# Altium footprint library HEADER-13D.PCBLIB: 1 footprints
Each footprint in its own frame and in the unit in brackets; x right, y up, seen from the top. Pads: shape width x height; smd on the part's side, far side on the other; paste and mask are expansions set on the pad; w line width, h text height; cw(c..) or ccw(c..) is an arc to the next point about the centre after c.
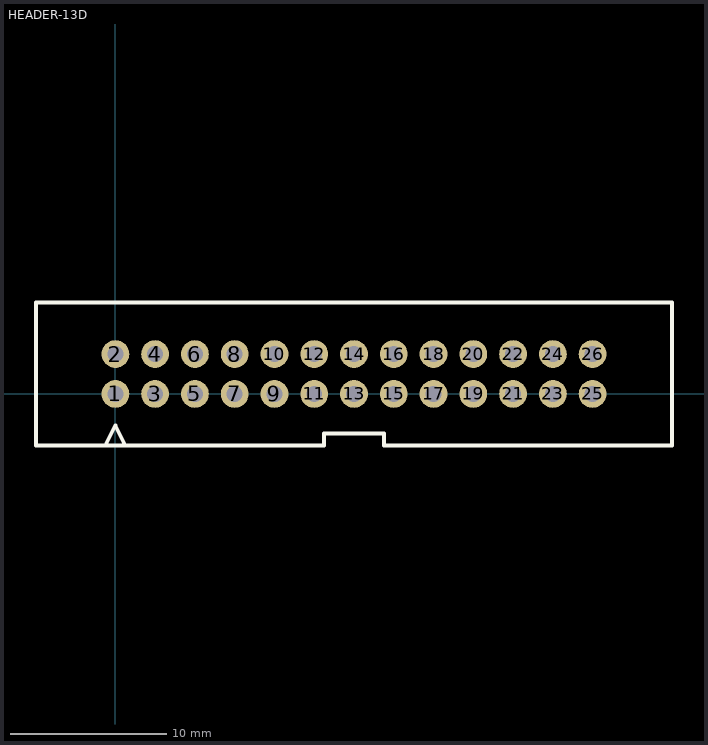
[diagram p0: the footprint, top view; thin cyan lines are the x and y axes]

## HEADER-13D [mil] "WWW.OURAVR.COM"
pads (26):
  round 70 hole 40: 1(0,0) 2(0,100) 3(100,0) 4(100,100) 5(200,0) 6(200,100) 7(300,0) 8(300,100) 9(400,0) 10(400,100) 11(500,0) 12(500,100) 13(600,0) 14(600,100) 15(700,0) 16(700,100) 17(800,0) 18(800,100) 19(900,0) 20(900,100) 21(1000,0) 22(1000,100) 23(1100,0) 24(1100,100) 25(1200,0) 26(1200,100)
Top Overlay:
  lines w10: -25,-130 0,-80 25,-130 ; -200,-130 -200,230 1400,230 1400,-130 675,-130 675,-100 525,-100 525,-130 -200,-130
